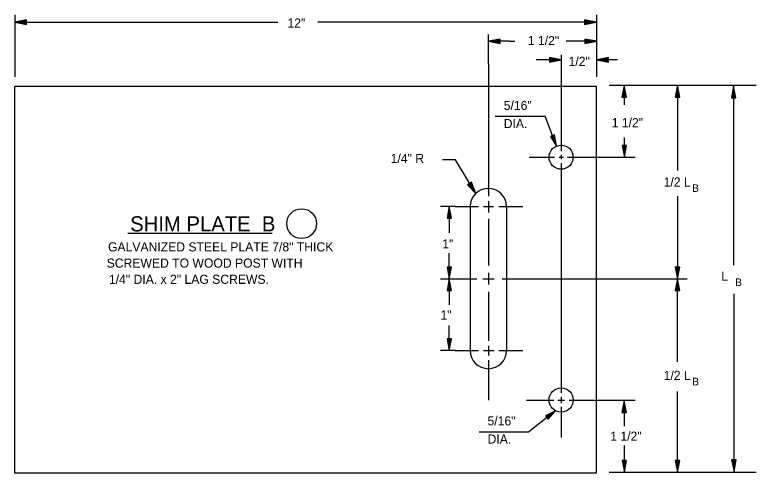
# Model space of a CAD drawing. Extents: x 51.3 to 58.6, y 21.9 to 32.
# Drawn here: x 52.735 to 57.627, y 28.93 to 31.956 of the extents above; entities that cross this region are included whole.
import ezdxf

# ---------------------------------------------------------------- set-up
doc = ezdxf.new("R2010")
doc.units = 0
for name, color, linetype in [('DETL-DIMS', 7, 'Continuous'), ('DETL-LINE', 7, 'Continuous'), ('DETL-NOTE', 7, 'Continuous'), ('DETL-TITL', 7, 'Continuous')]:
    doc.layers.add(name, color=color, linetype=linetype)

msp = doc.modelspace()

# ---------------------------------------------------------------- linework, layer by layer
at = {"layer": 'DETL-DIMS'}
for p, q in [((52.7371, 31.7308), (52.7371, 31.9558)), ((56.5751, 31.7308), (56.5751, 31.9558)), ((52.7351, 31.9068), (54.4711, 31.9068)), ((56.5711, 31.9068), (54.7341, 31.9068)), ((55.8601, 31.6328), (55.8601, 31.8258)), ((55.9981, 31.7808), (55.8601, 31.7808)), ((55.9981, 31.7808), (56.0341, 31.7808)), ((56.4121, 31.7808), (56.3731, 31.7808)), ((56.5751, 31.7808), (56.4121, 31.7808)), ((52.7371, 31.5458), (52.7371, 31.7308)), ((56.5751, 31.5458), (56.5751, 31.7308)), ((56.3401, 31.6578), (56.1761, 31.6578)), ((56.3401, 31.6908), (56.3401, 31.0558)), ((56.7121, 31.6578), (56.5751, 31.6578)), ((55.8601, 31.6328), (55.8601, 30.7578)), ((56.6571, 31.4908), (57.6269, 31.4908)), ((56.7561, 31.4888), (56.7561, 31.3608)), ((57.1079, 31.4908), (57.1079, 30.9276)), ((57.4779, 31.4848), (57.4779, 30.3034)), ((55.905, 31.2857), (56.2335, 31.2857)), ((56.3095, 31.0895), (56.2335, 31.2857)), ((56.7571, 31.0158), (56.7571, 31.1448)), ((56.1281, 31.0158), (56.2961, 31.0158)), ((56.3271, 31.0158), (56.3561, 31.0158)), ((56.3401, 31.0308), (56.3401, 31.0028)), ((56.3821, 31.0158), (56.8281, 31.0158)), ((55.6421, 30.9978), (55.5571, 30.9978)), ((55.7767, 30.7766), (55.6421, 30.9978)), ((56.3401, 30.9758), (56.3401, 29.4608)), ((55.8601, 30.7248), (55.8601, 30.6498)), ((57.1079, 30.7592), (57.1079, 30.2138)), ((55.6401, 30.6908), (55.5431, 30.6908)), ((55.6021, 30.6908), (55.6021, 30.5168)), ((55.6401, 30.6908), (55.7951, 30.6908)), ((55.8271, 30.6908), (55.8941, 30.6908)), ((55.9281, 30.6908), (56.0881, 30.6908)), ((55.8601, 30.6088), (55.8601, 30.3008)), ((55.6021, 30.2138), (55.6021, 30.3828)), ((55.8601, 30.2518), (55.8601, 30.1758)), ((55.5431, 30.2138), (55.7841, 30.2138)), ((55.6021, 30.2138), (55.6021, 30.0408)), ((55.8241, 30.2138), (55.8991, 30.2138)), ((55.9501, 30.2138), (57.0969, 30.2138)), ((57.0969, 30.2138), (57.1709, 30.2138)), ((57.1079, 29.6642), (57.1079, 30.2138)), ((55.8601, 30.1278), (55.8601, 29.8028)), ((57.4809, 29.5388), (57.4809, 30.1146)), ((55.6021, 29.7398), (55.6021, 29.9058)), ((55.8601, 29.7708), (55.8601, 29.7058)), ((55.6401, 29.7398), (55.5431, 29.7398)), ((55.6401, 29.7398), (55.7951, 29.7398)), ((55.8271, 29.7398), (55.8991, 29.7398)), ((55.9281, 29.7398), (56.0881, 29.7398)), ((55.8601, 29.6748), (55.8601, 29.4128)), ((57.4809, 29.1408), (57.4809, 29.5388)), ((57.1079, 28.9368), (57.1079, 29.4699)), ((56.1121, 29.4128), (56.2921, 29.4128)), ((56.3181, 29.4128), (56.3631, 29.4128)), ((56.3401, 29.4328), (56.3401, 29.3918)), ((56.3921, 29.4128), (56.8281, 29.4128)), ((56.7571, 29.2393), (56.7571, 29.4128)), ((56.3401, 29.3668), (56.3401, 29.1658)), ((56.3036, 29.342), (56.1267, 29.2032)), ((55.7982, 29.2032), (56.1267, 29.2032)), ((56.7571, 28.9358), (56.7571, 29.112)), ((57.4809, 28.9398), (57.4809, 29.1408)), ((56.6571, 28.9368), (57.6269, 28.9368))]:
    msp.add_line(p, q, dxfattribs=at)
for points in [[(52.8121, 31.9218), (52.7351, 31.9068), (52.8121, 31.8908), (52.8121, 31.9218)], [(52.8111, 31.9198), (52.7451, 31.9068), (52.8111, 31.8938), (52.8111, 31.9198)], [(52.8081, 31.9168), (52.7551, 31.9068), (52.8081, 31.8958), (52.8081, 31.9168)], [(52.8071, 31.9148), (52.7651, 31.9068), (52.8071, 31.8988), (52.8071, 31.9148)], [(52.8051, 31.9118), (52.7761, 31.9068), (52.8051, 31.9008), (52.8051, 31.9118)], [(52.8031, 31.9098), (52.7861, 31.9068), (52.8031, 31.9028), (52.8031, 31.9098)], [(52.8011, 31.9078), (52.7961, 31.9068), (52.8011, 31.9058), (52.8011, 31.9078)], [(56.4951, 31.8908), (56.5711, 31.9068), (56.4951, 31.9218), (56.4951, 31.8908)], [(56.4961, 31.8938), (56.5611, 31.9068), (56.4961, 31.9198), (56.4961, 31.8938)], [(56.4981, 31.8958), (56.5511, 31.9068), (56.4981, 31.9168), (56.4981, 31.8958)], [(56.5001, 31.8988), (56.5421, 31.9068), (56.5001, 31.9148), (56.5001, 31.8988)], [(56.5021, 31.9008), (56.5321, 31.9068), (56.5021, 31.9118), (56.5021, 31.9008)], [(56.5031, 31.9028), (56.5221, 31.9068), (56.5031, 31.9098), (56.5031, 31.9028)], [(56.5061, 31.9058), (56.5111, 31.9068), (56.5061, 31.9078), (56.5061, 31.9058)], [(55.9371, 31.7958), (55.8601, 31.7808), (55.9371, 31.7658), (55.9371, 31.7958)], [(55.9361, 31.7928), (55.8701, 31.7808), (55.9361, 31.7678), (55.9361, 31.7928)], [(55.9331, 31.7908), (55.8801, 31.7808), (55.9331, 31.7708), (55.9331, 31.7908)], [(55.9321, 31.7898), (55.8901, 31.7808), (55.9321, 31.7728), (55.9321, 31.7898)], [(55.9301, 31.7868), (55.9011, 31.7808), (55.9301, 31.7758), (55.9301, 31.7868)], [(55.9281, 31.7848), (55.9111, 31.7808), (55.9281, 31.7778), (55.9281, 31.7848)], [(55.9261, 31.7818), (55.9211, 31.7808), (55.9261, 31.7798), (55.9261, 31.7818)], [(56.4971, 31.7658), (56.5751, 31.7808), (56.4971, 31.7958), (56.4971, 31.7658)], [(56.5001, 31.7678), (56.5651, 31.7808), (56.5001, 31.7928), (56.5001, 31.7678)], [(56.5011, 31.7708), (56.5541, 31.7808), (56.5011, 31.7908), (56.5011, 31.7708)], [(56.5031, 31.7728), (56.5441, 31.7808), (56.5031, 31.7898), (56.5031, 31.7728)], [(56.5051, 31.7758), (56.5341, 31.7808), (56.5051, 31.7868), (56.5051, 31.7758)], [(56.5071, 31.7778), (56.5241, 31.7808), (56.5071, 31.7848), (56.5071, 31.7778)], [(56.5081, 31.7798), (56.5141, 31.7808), (56.5081, 31.7818), (56.5081, 31.7798)], [(56.2621, 31.6428), (56.3401, 31.6578), (56.2621, 31.6738), (56.2621, 31.6428)], [(56.2651, 31.6458), (56.3301, 31.6578), (56.2651, 31.6708), (56.2651, 31.6458)], [(56.2671, 31.6478), (56.3201, 31.6578), (56.2671, 31.6688), (56.2671, 31.6478)], [(56.2691, 31.6508), (56.3101, 31.6578), (56.2691, 31.6658), (56.2691, 31.6508)], [(56.2701, 31.6518), (56.2991, 31.6578), (56.2701, 31.6628), (56.2701, 31.6518)], [(56.2721, 31.6548), (56.2891, 31.6578), (56.2721, 31.6608), (56.2721, 31.6548)], [(56.2741, 31.6568), (56.2791, 31.6578), (56.2741, 31.6598), (56.2741, 31.6568)], [(56.6521, 31.6738), (56.5751, 31.6578), (56.6521, 31.6428), (56.6521, 31.6738)], [(56.6501, 31.6708), (56.5851, 31.6578), (56.6501, 31.6458), (56.6501, 31.6708)], [(56.6491, 31.6688), (56.5951, 31.6578), (56.6491, 31.6478), (56.6491, 31.6688)], [(56.6471, 31.6658), (56.6041, 31.6578), (56.6471, 31.6508), (56.6471, 31.6658)], [(56.6451, 31.6628), (56.6141, 31.6578), (56.6451, 31.6518), (56.6451, 31.6628)], [(56.6421, 31.6608), (56.6251, 31.6578), (56.6421, 31.6548), (56.6421, 31.6608)], [(56.6421, 31.6598), (56.6351, 31.6578), (56.6421, 31.6568), (56.6421, 31.6598)], [(56.7721, 31.4118), (56.7561, 31.4888), (56.7411, 31.4118), (56.7721, 31.4118)], [(56.7691, 31.4138), (56.7561, 31.4788), (56.7431, 31.4138), (56.7691, 31.4138)], [(56.7661, 31.4158), (56.7561, 31.4678), (56.7461, 31.4158), (56.7661, 31.4158)], [(56.7631, 31.4168), (56.7561, 31.4598), (56.7481, 31.4168), (56.7631, 31.4168)], [(57.1229, 31.4128), (57.1079, 31.4908), (57.0919, 31.4128), (57.1229, 31.4128)], [(57.1199, 31.4158), (57.1079, 31.4808), (57.0939, 31.4158), (57.1199, 31.4158)], [(57.1179, 31.4158), (57.1079, 31.4708), (57.0969, 31.4158), (57.1179, 31.4158)], [(57.1149, 31.4188), (57.1079, 31.4598), (57.0989, 31.4188), (57.1149, 31.4188)], [(57.4929, 31.4068), (57.4779, 31.4848), (57.4639, 31.4068), (57.4929, 31.4068)], [(57.4909, 31.4098), (57.4779, 31.4748), (57.4649, 31.4098), (57.4909, 31.4098)], [(57.4879, 31.4108), (57.4779, 31.4648), (57.4679, 31.4108), (57.4879, 31.4108)], [(56.7611, 31.4198), (56.7561, 31.4488), (56.7501, 31.4198), (56.7611, 31.4198)], [(56.7581, 31.4208), (56.7561, 31.4388), (56.7521, 31.4208), (56.7581, 31.4208)], [(56.7571, 31.4238), (56.7561, 31.4288), (56.7551, 31.4238), (56.7571, 31.4238)], [(57.1129, 31.4208), (57.1079, 31.4498), (57.1009, 31.4208), (57.1129, 31.4208)], [(57.1099, 31.4228), (57.1079, 31.4398), (57.1039, 31.4228), (57.1099, 31.4228)], [(57.1089, 31.4248), (57.1079, 31.4298), (57.1059, 31.4248), (57.1089, 31.4248)], [(57.4869, 31.4138), (57.4779, 31.4538), (57.4699, 31.4138), (57.4869, 31.4138)], [(57.4839, 31.4148), (57.4779, 31.4438), (57.4729, 31.4148), (57.4839, 31.4148)], [(57.4819, 31.4168), (57.4779, 31.4338), (57.4759, 31.4168), (57.4819, 31.4168)], [(57.4789, 31.4188), (57.4779, 31.4238), (57.4769, 31.4188), (57.4789, 31.4188)], [(56.2698, 31.1528), (56.3095, 31.0895), (56.297, 31.1624), (56.2698, 31.1528)], [(56.2726, 31.1525), (56.3053, 31.0977), (56.2946, 31.1605), (56.2726, 31.1525)], [(56.2753, 31.1509), (56.3027, 31.1086), (56.2931, 31.1592), (56.2753, 31.1509)], [(56.2774, 31.15), (56.2992, 31.116), (56.2922, 31.1571), (56.2774, 31.15)], [(56.2808, 31.1489), (56.2951, 31.1256), (56.2912, 31.1537), (56.2808, 31.1489)], [(56.2822, 31.1488), (56.293, 31.1343), (56.2888, 31.1503), (56.2822, 31.1488)], [(56.2857, 31.1478), (56.2881, 31.1433), (56.2879, 31.1483), (56.2857, 31.1478)], [(56.7421, 31.0928), (56.7571, 31.0158), (56.7721, 31.0928), (56.7421, 31.0928)], [(56.7441, 31.0908), (56.7571, 31.0258), (56.7701, 31.0908), (56.7441, 31.0908)], [(56.7471, 31.0898), (56.7571, 31.0358), (56.7671, 31.0898), (56.7471, 31.0898)], [(56.7501, 31.0868), (56.7571, 31.0448), (56.7651, 31.0868), (56.7501, 31.0868)], [(56.7511, 31.0858), (56.7571, 31.0558), (56.7621, 31.0858), (56.7511, 31.0858)], [(56.7531, 31.0828), (56.7571, 31.0658), (56.7601, 31.0828), (56.7531, 31.0828)], [(56.7561, 31.0818), (56.7571, 31.0758), (56.7581, 31.0818), (56.7561, 31.0818)], [(55.7225, 30.8344), (55.7765, 30.7764), (55.7485, 30.8504), (55.7225, 30.8344)], [(55.7265, 30.8344), (55.7715, 30.7844), (55.7485, 30.8464), (55.7265, 30.8344)], [(55.7295, 30.8344), (55.7665, 30.7934), (55.7465, 30.8444), (55.7295, 30.8344)], [(55.7315, 30.8334), (55.7615, 30.8024), (55.7465, 30.8414), (55.7315, 30.8334)], [(55.7355, 30.8334), (55.7565, 30.8114), (55.7445, 30.8394), (55.7355, 30.8334)], [(55.7375, 30.8334), (55.7515, 30.8194), (55.7445, 30.8364), (55.7375, 30.8334)], [(55.7405, 30.8314), (55.7445, 30.8284), (55.7435, 30.8334), (55.7405, 30.8314)], [(55.6171, 30.6128), (55.6021, 30.6908), (55.5881, 30.6128), (55.6171, 30.6128)], [(55.6151, 30.6158), (55.6021, 30.6808), (55.5891, 30.6158), (55.6151, 30.6158)], [(55.6121, 30.6158), (55.6021, 30.6708), (55.5921, 30.6158), (55.6121, 30.6158)], [(55.6111, 30.6188), (55.6021, 30.6598), (55.5941, 30.6188), (55.6111, 30.6188)], [(55.6081, 30.6208), (55.6021, 30.6498), (55.5971, 30.6208), (55.6081, 30.6208)], [(55.6061, 30.6228), (55.6021, 30.6398), (55.6001, 30.6228), (55.6061, 30.6228)], [(55.6031, 30.6238), (55.6021, 30.6298), (55.6011, 30.6238), (55.6031, 30.6238)], [(55.5881, 30.2908), (55.6021, 30.2138), (55.6171, 30.2908), (55.5881, 30.2908)], [(55.5891, 30.2908), (55.6021, 30.2238), (55.6151, 30.2908), (55.5891, 30.2908)], [(55.5921, 30.2878), (55.6021, 30.2338), (55.6121, 30.2878), (55.5921, 30.2878)], [(55.5941, 30.2858), (55.6021, 30.2438), (55.6111, 30.2858), (55.5941, 30.2858)], [(55.5971, 30.2838), (55.6021, 30.2548), (55.6081, 30.2838), (55.5971, 30.2838)], [(55.6001, 30.2818), (55.6021, 30.2648), (55.6061, 30.2818), (55.6001, 30.2818)], [(57.0919, 30.2908), (57.1079, 30.2138), (57.1229, 30.2908), (57.0919, 30.2908)], [(57.0939, 30.2908), (57.1079, 30.2238), (57.1199, 30.2908), (57.0939, 30.2908)], [(57.0969, 30.2878), (57.1079, 30.2338), (57.1179, 30.2878), (57.0969, 30.2878)], [(57.0989, 30.2858), (57.1079, 30.2438), (57.1149, 30.2858), (57.0989, 30.2858)], [(57.1009, 30.2838), (57.1079, 30.2548), (57.1129, 30.2838), (57.1009, 30.2838)], [(57.1039, 30.2818), (57.1079, 30.2648), (57.1099, 30.2818), (57.1039, 30.2818)], [(55.6011, 30.2798), (55.6021, 30.2748), (55.6031, 30.2798), (55.6011, 30.2798)], [(57.1059, 30.2798), (57.1079, 30.2748), (57.1089, 30.2798), (57.1059, 30.2798)], [(55.6171, 30.1368), (55.6021, 30.2138), (55.5881, 30.1368), (55.6171, 30.1368)], [(55.6151, 30.1388), (55.6021, 30.2038), (55.5891, 30.1388), (55.6151, 30.1388)], [(55.6121, 30.1408), (55.6021, 30.1928), (55.5921, 30.1408), (55.6121, 30.1408)], [(55.6111, 30.1418), (55.6021, 30.1848), (55.5941, 30.1418), (55.6111, 30.1418)], [(57.1229, 30.1358), (57.1079, 30.2138), (57.0919, 30.1358), (57.1229, 30.1358)], [(57.1199, 30.1388), (57.1079, 30.2038), (57.0939, 30.1388), (57.1199, 30.1388)], [(57.1179, 30.1388), (57.1079, 30.1938), (57.0969, 30.1388), (57.1179, 30.1388)], [(57.1149, 30.1418), (57.1079, 30.1828), (57.0989, 30.1418), (57.1149, 30.1418)], [(55.6081, 30.1448), (55.6021, 30.1738), (55.5971, 30.1448), (55.6081, 30.1448)], [(55.6061, 30.1458), (55.6021, 30.1638), (55.6001, 30.1458), (55.6061, 30.1458)], [(55.6031, 30.1488), (55.6021, 30.1538), (55.6011, 30.1488), (55.6031, 30.1488)], [(57.1129, 30.1438), (57.1079, 30.1728), (57.1009, 30.1438), (57.1129, 30.1438)], [(57.1099, 30.1458), (57.1079, 30.1628), (57.1039, 30.1458), (57.1099, 30.1458)], [(57.1089, 30.1478), (57.1079, 30.1528), (57.1059, 30.1478), (57.1089, 30.1478)], [(55.5881, 29.8168), (55.6021, 29.7398), (55.6171, 29.8168), (55.5881, 29.8168)], [(55.5891, 29.8148), (55.6021, 29.7498), (55.6151, 29.8148), (55.5891, 29.8148)], [(55.5921, 29.8128), (55.6021, 29.7598), (55.6121, 29.8128), (55.5921, 29.8128)], [(55.5941, 29.8108), (55.6021, 29.7688), (55.6111, 29.8108), (55.5941, 29.8108)], [(55.5971, 29.8098), (55.6021, 29.7788), (55.6081, 29.8098), (55.5971, 29.8098)], [(55.6001, 29.8068), (55.6021, 29.7888), (55.6061, 29.8068), (55.6001, 29.8068)], [(55.6011, 29.8058), (55.6021, 29.7998), (55.6031, 29.8058), (55.6011, 29.8058)], [(56.7721, 29.3308), (56.7561, 29.4078), (56.7411, 29.3308), (56.7721, 29.3308)], [(56.7691, 29.3328), (56.7561, 29.3978), (56.7431, 29.3328), (56.7691, 29.3328)], [(56.7661, 29.3358), (56.7561, 29.3868), (56.7461, 29.3358), (56.7661, 29.3358)], [(56.7631, 29.3358), (56.7561, 29.3788), (56.7481, 29.3358), (56.7631, 29.3358)], [(56.7611, 29.3388), (56.7561, 29.3678), (56.7501, 29.3388), (56.7611, 29.3388)], [(56.7581, 29.3408), (56.7561, 29.3578), (56.7521, 29.3408), (56.7581, 29.3408)], [(56.2547, 29.2856), (56.3036, 29.342), (56.2376, 29.3088), (56.2547, 29.2856)], [(56.2541, 29.2884), (56.297, 29.3356), (56.2401, 29.3071), (56.2541, 29.2884)], [(56.2549, 29.2914), (56.2873, 29.33), (56.2417, 29.306), (56.2549, 29.2914)], [(56.2551, 29.2937), (56.2813, 29.3244), (56.244, 29.3058), (56.2551, 29.2937)], [(56.2551, 29.2973), (56.2733, 29.3177), (56.2476, 29.3058), (56.2551, 29.2973)], [(56.2548, 29.2987), (56.2655, 29.3132), (56.2515, 29.3045), (56.2548, 29.2987)], [(56.2548, 29.3023), (56.2584, 29.3059), (56.2537, 29.3042), (56.2548, 29.3023)], [(56.7571, 29.3428), (56.7561, 29.3478), (56.7551, 29.3428), (56.7571, 29.3428)], [(56.7421, 29.0138), (56.7571, 28.9358), (56.7721, 29.0138), (56.7421, 29.0138)], [(56.7421, 29.0138), (56.7571, 28.9358), (56.7721, 29.0138), (56.7421, 29.0138)], [(56.7441, 29.0108), (56.7571, 28.9458), (56.7701, 29.0108), (56.7441, 29.0108)], [(56.7441, 29.0108), (56.7571, 28.9458), (56.7701, 29.0108), (56.7441, 29.0108)], [(56.7471, 29.0098), (56.7571, 28.9558), (56.7671, 29.0098), (56.7471, 29.0098)], [(56.7471, 29.0098), (56.7571, 28.9558), (56.7671, 29.0098), (56.7471, 29.0098)], [(57.0919, 29.0138), (57.1079, 28.9368), (57.1229, 29.0138), (57.0919, 29.0138)], [(57.0939, 29.0138), (57.1079, 28.9468), (57.1199, 29.0138), (57.0939, 29.0138)], [(57.0969, 29.0108), (57.1079, 28.9568), (57.1179, 29.0108), (57.0969, 29.0108)], [(57.0989, 29.0088), (57.1079, 28.9668), (57.1149, 29.0088), (57.0989, 29.0088)], [(57.4649, 29.0178), (57.4809, 28.9398), (57.4959, 29.0178), (57.4649, 29.0178)], [(57.4679, 29.0158), (57.4809, 28.9508), (57.4929, 29.0158), (57.4679, 29.0158)], [(57.4699, 29.0138), (57.4809, 28.9608), (57.4909, 29.0138), (57.4699, 29.0138)], [(57.4729, 29.0108), (57.4809, 28.9688), (57.4879, 29.0108), (57.4729, 29.0108)], [(57.4739, 29.0098), (57.4809, 28.9798), (57.4859, 29.0098), (57.4739, 29.0098)], [(56.7501, 29.0068), (56.7571, 28.9658), (56.7651, 29.0068), (56.7501, 29.0068)], [(56.7501, 29.0068), (56.7571, 28.9658), (56.7651, 29.0068), (56.7501, 29.0068)], [(56.7511, 29.0058), (56.7571, 28.9758), (56.7621, 29.0058), (56.7511, 29.0058)], [(56.7511, 29.0058), (56.7571, 28.9758), (56.7621, 29.0058), (56.7511, 29.0058)], [(56.7531, 29.0038), (56.7571, 28.9858), (56.7601, 29.0038), (56.7531, 29.0038)], [(56.7531, 29.0038), (56.7571, 28.9858), (56.7601, 29.0038), (56.7531, 29.0038)], [(56.7561, 29.0018), (56.7571, 28.9958), (56.7581, 29.0018), (56.7561, 29.0018)], [(56.7561, 29.0018), (56.7571, 28.9958), (56.7581, 29.0018), (56.7561, 29.0018)], [(57.1009, 29.0068), (57.1079, 28.9778), (57.1129, 29.0068), (57.1009, 29.0068)], [(57.1039, 29.0048), (57.1079, 28.9878), (57.1099, 29.0048), (57.1039, 29.0048)], [(57.1059, 29.0028), (57.1079, 28.9978), (57.1089, 29.0028), (57.1059, 29.0028)], [(57.4769, 29.0068), (57.4809, 28.9898), (57.4829, 29.0068), (57.4769, 29.0068)], [(57.4789, 29.0058), (57.4809, 28.9998), (57.4819, 29.0058), (57.4789, 29.0058)]]:
    msp.add_lwpolyline(points, dxfattribs=at)
at = {"layer": 'DETL-LINE'}
for p, q in [((52.7361, 28.9298), (52.7361, 31.4838)), ((52.7361, 31.4838), (56.5721, 31.4838)), ((56.5721, 31.4838), (56.5721, 28.9298)), ((55.7401, 30.6908), (55.7401, 29.7398)), ((55.9791, 30.6908), (55.9791, 29.7398)), ((56.5721, 28.9298), (52.7361, 28.9298))]:
    msp.add_line(p, q, dxfattribs=at)
for centre in [(56.3399, 31.0159), (56.3399, 29.4129)]:
    msp.add_circle(centre, 0.0797, dxfattribs=at)
for centre, start, end in [((55.8595, 30.6903), 0, 180), ((55.8595, 29.7392), 180, 0)]:
    msp.add_arc(centre, 0.1195, start, end, dxfattribs=at)
at = {"layer": 'DETL-NOTE'}
msp.add_circle((54.6276, 30.5771), 0.0983, dxfattribs=at)
at = {"layer": 'DETL-TITL'}
msp.add_line((53.4799, 30.5136), (54.4321, 30.5136), dxfattribs=at)

# ---------------------------------------------------------------- texts
at = {"layer": 'DETL-NOTE'}
for s, p in [('12"', (54.5341, 31.8718)), ('1 1/2"', (56.1201, 31.7558)), ('1/2"', (56.3891, 31.6188)), ('5/16"', (55.9612, 31.3277)), ('DIA.', (55.9612, 31.2077)), ('1/4" R', (55.2151, 30.9778)), ('GALVANIZED STEEL PLATE 7/8" THICK', (53.3501, 30.3938)), ('SCREWED TO WOOD POST WITH', (53.3411, 30.2868)), ('1/4" DIA. x 2" LAG SCREWS.', (53.3561, 30.1798)), ('5/16"', (55.8544, 29.2452)), ('DIA.', (55.8544, 29.1252))]:
    msp.add_text(s, height=0.06, dxfattribs=at).set_placement(p)
for s, height, p in [('1 1/2"', 0.06, (56.6736, 31.2138)), ('1/2 L', 0.06, (57.0166, 30.8223)), ('B', 0.05, (57.2049, 30.7867)), ('1"', 0.06, (55.5556, 30.4133)), (' L', 0.06, (57.3739, 30.2009)), ('B', 0.05, (57.4883, 30.1653)), ('1"', 0.06, (55.5437, 29.9438)), ('1/2 L', 0.06, (57.0166, 29.5453)), ('B', 0.05, (57.2049, 29.5097)), ('1 1/2"', 0.06, (56.6642, 29.1443))]:
    msp.add_text(s, height=height, rotation=360, dxfattribs=at).set_placement(p)
at = {"layer": 'DETL-TITL'}
msp.add_text('SHIM PLATE  B', height=0.100002, dxfattribs=at).set_placement((53.4961, 30.5258))

doc.saveas('drawing.dxf')
